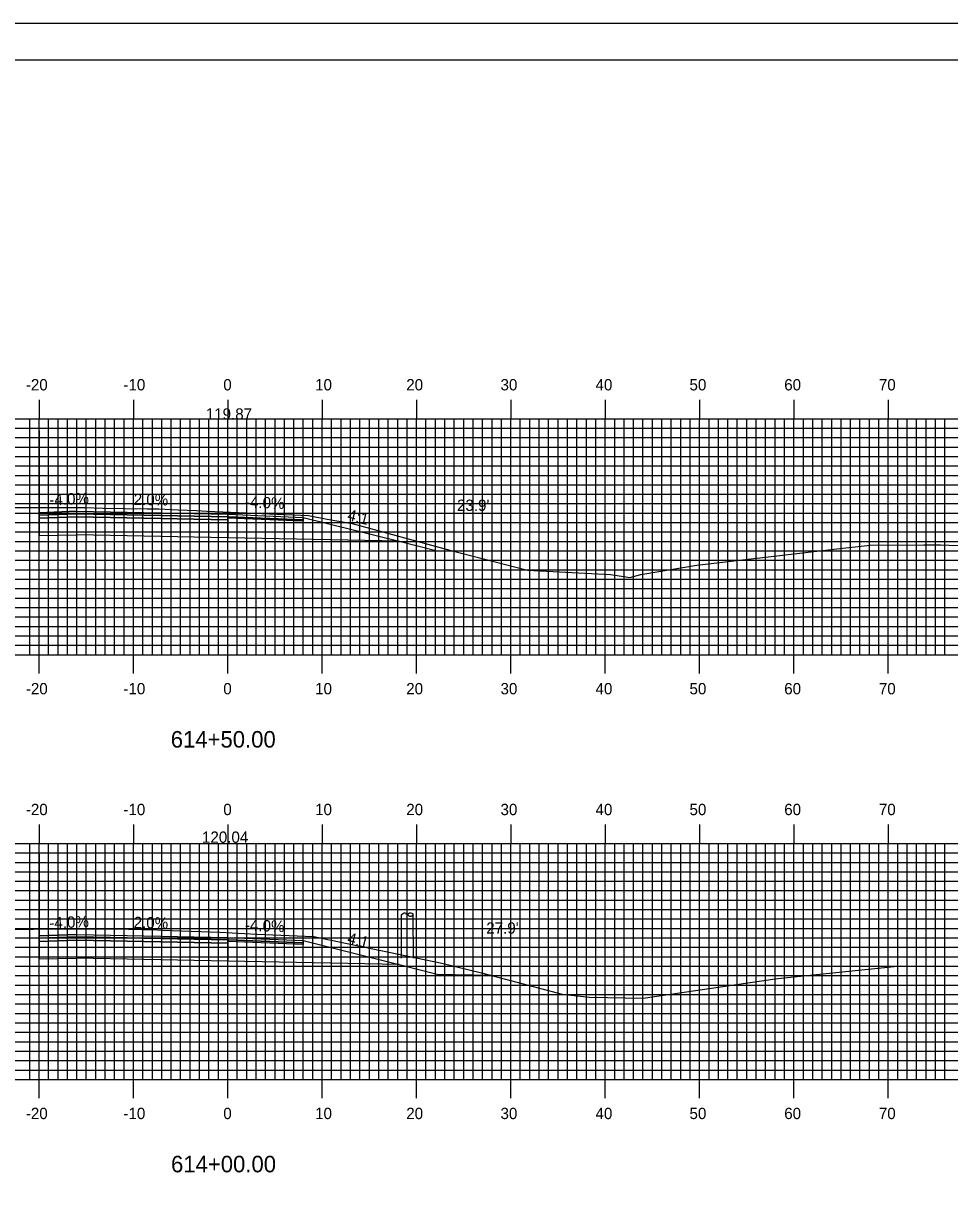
# Model space of a CAD drawing. Extents: x 844143 to 844486, y 363538 to 363758.
# Drawn here: x 844286.8 to 844385, y 363633.7 to 363757.6 of the extents above; entities that cross this region are included whole.
import ezdxf

# ---------------------------------------------------------------- set-up
doc = ezdxf.new("R2010")
doc.units = 0
for name, color, linetype in [('ANNOTATION', 7, 'Continuous'), ('BORDER', 7, 'Continuous'), ('D_Roadway_Centerline', 7, 'Continuous'), ('D_Roadway_Centerline_Text', 7, 'Continuous'), ('D_Roadway_Edge_Shoulder', 7, 'Continuous'), ('D_Roadway_Edge_TW', 7, 'Continuous'), ('D_Roadway_FinishedGrade', 7, 'Continuous'), ('D_Roadway_Pavement', 7, 'Continuous'), ('D_Roadway_SubGrade', 7, 'Continuous'), ('D_Text_Standard', 7, 'Continuous'), ('H_V ANNOTATION', 7, 'Continuous'), ('M_Roadway_Centerline', 7, 'Continuous'), ('MAJOR', 7, 'Continuous'), ('MINOR', 7, 'Continuous'), ('PLOT BOUNDARY', 7, 'Continuous'), ('S_Roadway_Centerline', 7, 'Continuous'), ('S_Utilities_Pole_StreetLight', 7, 'Continuous')]:
    doc.layers.add(name, color=color, linetype=linetype)

msp = doc.modelspace()

# ---------------------------------------------------------------- linework, layer by layer
at = {"layer": 'BORDER'}
msp.add_lwpolyline([(844158.85, 363543.72), (844478.85, 363543.72), (844478.85, 363753.72), (844158.85, 363753.72)], close=True, dxfattribs=at)
at = {"layer": 'D_Roadway_Centerline'}
for points in [[(844288.45, 363705.75), (844288.45, 363705.75), (844292.45, 363705.91), (844308.45, 363705.59), (844316.45, 363705.27), (844326.62, 363702.73)], [(844288.45, 363660.92), (844292.45, 363661.08), (844308.45, 363660.76), (844316.45, 363660.44), (844326.62, 363657.89)]]:
    msp.add_lwpolyline(points, dxfattribs=at)
at = {"layer": 'D_Roadway_Edge_Shoulder'}
for points in [[(844292.45, 363705.91), (844288.45, 363705.75), (844288.45, 363705.5), (844292.45, 363705.66)], [(844308.45, 363705.59), (844316.45, 363705.27), (844316.45, 363705.02), (844308.45, 363705.34)], [(844292.45, 363661.08), (844288.45, 363660.92), (844288.45, 363660.67), (844292.45, 363660.83)], [(844308.45, 363660.76), (844316.45, 363660.44), (844316.45, 363660.19), (844308.45, 363660.51)]]:
    msp.add_lwpolyline(points, close=True, dxfattribs=at)
at = {"layer": 'D_Roadway_Edge_TW'}
for points in [[(844292.45, 363705.91), (844308.45, 363705.59), (844308.45, 363705.34), (844292.45, 363705.66)], [(844292.45, 363661.08), (844308.45, 363660.76), (844308.45, 363660.51), (844292.45, 363660.83)]]:
    msp.add_lwpolyline(points, close=True, dxfattribs=at)
at = {"layer": 'D_Roadway_FinishedGrade'}
for points in [[(844326.62, 363702.73), (844330.62, 363701.73), (844332.31, 363701.7)], [(844326.62, 363657.89), (844330.62, 363656.89), (844336.33, 363656.78)]]:
    msp.add_lwpolyline(points, dxfattribs=at)
at = {"layer": 'D_Roadway_Pavement'}
for points in [[(844292.45, 363705.66), (844288.45, 363705.5), (844288.45, 363705.17), (844292.45, 363705.33)], [(844292.45, 363705.66), (844308.45, 363705.34), (844308.45, 363705.01), (844292.45, 363705.33)], [(844308.45, 363705.34), (844316.45, 363705.02), (844316.45, 363704.86), (844308.45, 363705.18)], [(844292.45, 363660.83), (844288.45, 363660.67), (844288.45, 363660.33), (844292.45, 363660.49)], [(844292.45, 363660.83), (844308.45, 363660.51), (844308.45, 363660.17), (844292.45, 363660.49)], [(844308.45, 363660.51), (844316.45, 363660.19), (844316.45, 363660.02), (844308.45, 363660.34)]]:
    msp.add_lwpolyline(points, close=True, dxfattribs=at)
for points in [[(844308.45, 363705.34), (844308.45, 363705.01)], [(844308.45, 363705.34), (844308.45, 363705.01)], [(844308.45, 363660.51), (844308.45, 363660.17)], [(844308.45, 363660.51), (844308.45, 363660.17)]]:
    msp.add_lwpolyline(points, dxfattribs=at)
at = {"layer": 'D_Roadway_SubGrade'}
for p, q in [((844288.45, 363714.43), (844288.45, 363703.33)), ((844288.45, 363669.59), (844288.45, 363658.5))]:
    msp.add_line(p, q, dxfattribs=at)
for points in [[(844292.45, 363705.33), (844288.45, 363705.17), (844288.45, 363705.5), (844288.45, 363705.75), (844288.45, 363703.33), (844292.45, 363703.41)], [(844292.45, 363705.33), (844308.45, 363705.01), (844308.45, 363703.09), (844292.45, 363703.41)], [(844308.45, 363705.01), (844308.45, 363705.34), (844316.45, 363705.02), (844316.45, 363705.27), (844326.62, 363702.73), (844308.45, 363703.09)], [(844292.45, 363660.49), (844288.45, 363660.33), (844288.45, 363660.67), (844288.45, 363660.92), (844288.45, 363658.5), (844292.45, 363658.58)], [(844292.45, 363660.49), (844308.45, 363660.17), (844308.45, 363658.26), (844292.45, 363658.58)], [(844308.45, 363660.17), (844308.45, 363660.51), (844316.45, 363660.19), (844316.45, 363660.44), (844326.62, 363657.89), (844308.45, 363658.26)]]:
    msp.add_lwpolyline(points, close=True, dxfattribs=at)
at = {"layer": 'MAJOR'}
for p, q in [((844288.45, 363717.73), (844288.45, 363715.72)), ((844298.45, 363717.73), (844298.45, 363715.72)), ((844308.45, 363717.73), (844308.45, 363715.72)), ((844318.45, 363717.73), (844318.45, 363715.72)), ((844328.45, 363717.73), (844328.45, 363715.72)), ((844338.45, 363717.73), (844338.45, 363715.72)), ((844348.45, 363717.73), (844348.45, 363715.72)), ((844358.45, 363717.73), (844358.45, 363715.72)), ((844368.45, 363717.73), (844368.45, 363715.72)), ((844378.45, 363717.73), (844378.45, 363715.72)), ((844168.45, 363715.72), (844448.45, 363715.72)), ((844168.45, 363715.72), (844448.45, 363715.72)), ((844288.45, 363690.72), (844288.45, 363715.72)), ((844298.45, 363690.72), (844298.45, 363715.72)), ((844308.45, 363690.72), (844308.45, 363715.72)), ((844318.45, 363690.72), (844318.45, 363715.72)), ((844328.45, 363690.72), (844328.45, 363715.72)), ((844338.45, 363690.72), (844338.45, 363715.72)), ((844348.45, 363690.72), (844348.45, 363715.72)), ((844358.45, 363690.72), (844358.45, 363715.72)), ((844368.45, 363690.72), (844368.45, 363715.72)), ((844378.45, 363690.72), (844378.45, 363715.72)), ((844168.45, 363710.72), (844448.45, 363710.72)), ((844168.45, 363705.72), (844448.45, 363705.72)), ((844168.45, 363700.72), (844448.45, 363700.72)), ((844168.45, 363695.72), (844448.45, 363695.72)), ((844168.45, 363690.72), (844448.45, 363690.72)), ((844168.45, 363690.72), (844448.45, 363690.72)), ((844288.45, 363688.72), (844288.45, 363690.72)), ((844298.45, 363688.72), (844298.45, 363690.72)), ((844308.45, 363688.72), (844308.45, 363690.72)), ((844318.45, 363688.72), (844318.45, 363690.72)), ((844328.45, 363688.72), (844328.45, 363690.72)), ((844338.45, 363688.72), (844338.45, 363690.72)), ((844348.45, 363688.72), (844348.45, 363690.72)), ((844358.45, 363688.72), (844358.45, 363690.72)), ((844368.45, 363688.72), (844368.45, 363690.72)), ((844378.45, 363688.72), (844378.45, 363690.72)), ((844288.45, 363672.73), (844288.45, 363670.72)), ((844298.45, 363672.73), (844298.45, 363670.72)), ((844308.45, 363672.73), (844308.45, 363670.72)), ((844318.45, 363672.73), (844318.45, 363670.72)), ((844328.45, 363672.73), (844328.45, 363670.72)), ((844338.45, 363672.73), (844338.45, 363670.72)), ((844348.45, 363672.73), (844348.45, 363670.72)), ((844358.45, 363672.73), (844358.45, 363670.72)), ((844368.45, 363672.73), (844368.45, 363670.72)), ((844378.45, 363672.73), (844378.45, 363670.72)), ((844168.45, 363670.72), (844448.45, 363670.72)), ((844168.45, 363670.72), (844448.45, 363670.72)), ((844288.45, 363645.72), (844288.45, 363670.72)), ((844298.45, 363645.72), (844298.45, 363670.72)), ((844308.45, 363645.72), (844308.45, 363670.72)), ((844318.45, 363645.72), (844318.45, 363670.72)), ((844328.45, 363645.72), (844328.45, 363670.72)), ((844338.45, 363645.72), (844338.45, 363670.72)), ((844348.45, 363645.72), (844348.45, 363670.72)), ((844358.45, 363645.72), (844358.45, 363670.72)), ((844368.45, 363645.72), (844368.45, 363670.72)), ((844378.45, 363645.72), (844378.45, 363670.72)), ((844168.45, 363665.72), (844448.45, 363665.72)), ((844168.45, 363660.72), (844448.45, 363660.72)), ((844168.45, 363655.72), (844448.45, 363655.72)), ((844168.45, 363650.72), (844448.45, 363650.72)), ((844168.45, 363645.72), (844448.45, 363645.72)), ((844168.45, 363645.72), (844448.45, 363645.72)), ((844288.45, 363643.72), (844288.45, 363645.72)), ((844298.45, 363643.72), (844298.45, 363645.72)), ((844308.45, 363643.72), (844308.45, 363645.72)), ((844318.45, 363643.72), (844318.45, 363645.72)), ((844328.45, 363643.72), (844328.45, 363645.72)), ((844338.45, 363643.72), (844338.45, 363645.72)), ((844348.45, 363643.72), (844348.45, 363645.72)), ((844358.45, 363643.72), (844358.45, 363645.72)), ((844368.45, 363643.72), (844368.45, 363645.72)), ((844378.45, 363643.72), (844378.45, 363645.72))]:
    msp.add_line(p, q, dxfattribs=at)
at = {"layer": 'MINOR'}
for p, q in [((844287.45, 363690.72), (844287.45, 363715.72)), ((844289.45, 363690.72), (844289.45, 363715.72)), ((844290.45, 363690.72), (844290.45, 363715.72)), ((844291.45, 363690.72), (844291.45, 363715.72)), ((844292.45, 363690.72), (844292.45, 363715.72)), ((844293.45, 363690.72), (844293.45, 363715.72)), ((844294.45, 363690.72), (844294.45, 363715.72)), ((844295.45, 363690.72), (844295.45, 363715.72)), ((844296.45, 363690.72), (844296.45, 363715.72)), ((844297.45, 363690.72), (844297.45, 363715.72)), ((844299.45, 363690.72), (844299.45, 363715.72)), ((844300.45, 363690.72), (844300.45, 363715.72)), ((844301.45, 363690.72), (844301.45, 363715.72)), ((844302.45, 363690.72), (844302.45, 363715.72)), ((844303.45, 363690.72), (844303.45, 363715.72)), ((844304.45, 363690.72), (844304.45, 363715.72)), ((844305.45, 363690.72), (844305.45, 363715.72)), ((844306.45, 363690.72), (844306.45, 363715.72)), ((844307.45, 363690.72), (844307.45, 363715.72)), ((844309.45, 363690.72), (844309.45, 363715.72)), ((844310.45, 363690.72), (844310.45, 363715.72)), ((844311.45, 363690.72), (844311.45, 363715.72)), ((844312.45, 363690.72), (844312.45, 363715.72)), ((844313.45, 363690.72), (844313.45, 363715.72)), ((844314.45, 363690.72), (844314.45, 363715.72)), ((844315.45, 363690.72), (844315.45, 363715.72)), ((844316.45, 363690.72), (844316.45, 363715.72)), ((844317.45, 363690.72), (844317.45, 363715.72)), ((844319.45, 363690.72), (844319.45, 363715.72)), ((844320.45, 363690.72), (844320.45, 363715.72)), ((844321.45, 363690.72), (844321.45, 363715.72)), ((844322.45, 363690.72), (844322.45, 363715.72)), ((844323.45, 363690.72), (844323.45, 363715.72)), ((844324.45, 363690.72), (844324.45, 363715.72)), ((844325.45, 363690.72), (844325.45, 363715.72)), ((844326.45, 363690.72), (844326.45, 363715.72)), ((844327.45, 363690.72), (844327.45, 363715.72)), ((844329.45, 363690.72), (844329.45, 363715.72)), ((844330.45, 363690.72), (844330.45, 363715.72)), ((844331.45, 363690.72), (844331.45, 363715.72)), ((844332.45, 363690.72), (844332.45, 363715.72)), ((844333.45, 363690.72), (844333.45, 363715.72)), ((844334.45, 363690.72), (844334.45, 363715.72)), ((844335.45, 363690.72), (844335.45, 363715.72)), ((844336.45, 363690.72), (844336.45, 363715.72)), ((844337.45, 363690.72), (844337.45, 363715.72)), ((844339.45, 363690.72), (844339.45, 363715.72)), ((844340.45, 363690.72), (844340.45, 363715.72)), ((844341.45, 363690.72), (844341.45, 363715.72)), ((844342.45, 363690.72), (844342.45, 363715.72)), ((844343.45, 363690.72), (844343.45, 363715.72)), ((844344.45, 363690.72), (844344.45, 363715.72)), ((844345.45, 363690.72), (844345.45, 363715.72)), ((844346.45, 363690.72), (844346.45, 363715.72)), ((844347.45, 363690.72), (844347.45, 363715.72)), ((844349.45, 363690.72), (844349.45, 363715.72)), ((844350.45, 363690.72), (844350.45, 363715.72)), ((844351.45, 363690.72), (844351.45, 363715.72)), ((844352.45, 363690.72), (844352.45, 363715.72)), ((844353.45, 363690.72), (844353.45, 363715.72)), ((844354.45, 363690.72), (844354.45, 363715.72)), ((844355.45, 363690.72), (844355.45, 363715.72)), ((844356.45, 363690.72), (844356.45, 363715.72)), ((844357.45, 363690.72), (844357.45, 363715.72)), ((844359.45, 363690.72), (844359.45, 363715.72)), ((844360.45, 363690.72), (844360.45, 363715.72)), ((844361.45, 363690.72), (844361.45, 363715.72)), ((844362.45, 363690.72), (844362.45, 363715.72)), ((844363.45, 363690.72), (844363.45, 363715.72)), ((844364.45, 363690.72), (844364.45, 363715.72)), ((844365.45, 363690.72), (844365.45, 363715.72)), ((844366.45, 363690.72), (844366.45, 363715.72)), ((844367.45, 363690.72), (844367.45, 363715.72)), ((844369.45, 363690.72), (844369.45, 363715.72)), ((844370.45, 363690.72), (844370.45, 363715.72)), ((844371.45, 363690.72), (844371.45, 363715.72)), ((844372.45, 363690.72), (844372.45, 363715.72)), ((844373.45, 363690.72), (844373.45, 363715.72)), ((844374.45, 363690.72), (844374.45, 363715.72)), ((844375.45, 363690.72), (844375.45, 363715.72)), ((844376.45, 363690.72), (844376.45, 363715.72)), ((844377.45, 363690.72), (844377.45, 363715.72)), ((844379.45, 363690.72), (844379.45, 363715.72)), ((844380.45, 363690.72), (844380.45, 363715.72)), ((844381.45, 363690.72), (844381.45, 363715.72)), ((844382.45, 363690.72), (844382.45, 363715.72)), ((844383.45, 363690.72), (844383.45, 363715.72)), ((844384.45, 363690.72), (844384.45, 363715.72)), ((844168.45, 363714.72), (844448.45, 363714.72)), ((844168.45, 363713.72), (844448.45, 363713.72)), ((844168.45, 363712.72), (844448.45, 363712.72)), ((844168.45, 363711.72), (844448.45, 363711.72)), ((844168.45, 363709.72), (844448.45, 363709.72)), ((844168.45, 363708.72), (844448.45, 363708.72)), ((844168.45, 363707.72), (844448.45, 363707.72)), ((844168.45, 363706.72), (844448.45, 363706.72)), ((844168.45, 363704.72), (844448.45, 363704.72)), ((844168.45, 363703.72), (844448.45, 363703.72)), ((844168.45, 363702.72), (844448.45, 363702.72)), ((844168.45, 363701.72), (844448.45, 363701.72)), ((844168.45, 363699.72), (844448.45, 363699.72)), ((844168.45, 363698.72), (844448.45, 363698.72)), ((844168.45, 363697.72), (844448.45, 363697.72)), ((844168.45, 363696.72), (844448.45, 363696.72)), ((844168.45, 363694.72), (844448.45, 363694.72)), ((844168.45, 363693.72), (844448.45, 363693.72)), ((844168.45, 363692.72), (844448.45, 363692.72)), ((844168.45, 363691.72), (844448.45, 363691.72)), ((844168.45, 363669.72), (844448.45, 363669.72)), ((844287.45, 363645.72), (844287.45, 363670.72)), ((844289.45, 363645.72), (844289.45, 363670.72)), ((844290.45, 363645.72), (844290.45, 363670.72)), ((844291.45, 363645.72), (844291.45, 363670.72)), ((844292.45, 363645.72), (844292.45, 363670.72)), ((844293.45, 363645.72), (844293.45, 363670.72)), ((844294.45, 363645.72), (844294.45, 363670.72)), ((844295.45, 363645.72), (844295.45, 363670.72)), ((844296.45, 363645.72), (844296.45, 363670.72)), ((844297.45, 363645.72), (844297.45, 363670.72)), ((844299.45, 363645.72), (844299.45, 363670.72)), ((844300.45, 363645.72), (844300.45, 363670.72)), ((844301.45, 363645.72), (844301.45, 363670.72)), ((844302.45, 363645.72), (844302.45, 363670.72)), ((844303.45, 363645.72), (844303.45, 363670.72)), ((844304.45, 363645.72), (844304.45, 363670.72)), ((844305.45, 363645.72), (844305.45, 363670.72)), ((844306.45, 363645.72), (844306.45, 363670.72)), ((844307.45, 363645.72), (844307.45, 363670.72)), ((844309.45, 363645.72), (844309.45, 363670.72)), ((844310.45, 363645.72), (844310.45, 363670.72)), ((844311.45, 363645.72), (844311.45, 363670.72)), ((844312.45, 363645.72), (844312.45, 363670.72)), ((844313.45, 363645.72), (844313.45, 363670.72)), ((844314.45, 363645.72), (844314.45, 363670.72)), ((844315.45, 363645.72), (844315.45, 363670.72)), ((844316.45, 363645.72), (844316.45, 363670.72)), ((844317.45, 363645.72), (844317.45, 363670.72)), ((844319.45, 363645.72), (844319.45, 363670.72)), ((844320.45, 363645.72), (844320.45, 363670.72)), ((844321.45, 363645.72), (844321.45, 363670.72)), ((844322.45, 363645.72), (844322.45, 363670.72)), ((844323.45, 363645.72), (844323.45, 363670.72)), ((844324.45, 363645.72), (844324.45, 363670.72)), ((844325.45, 363645.72), (844325.45, 363670.72)), ((844326.45, 363645.72), (844326.45, 363670.72)), ((844327.45, 363645.72), (844327.45, 363670.72)), ((844329.45, 363645.72), (844329.45, 363670.72)), ((844330.45, 363645.72), (844330.45, 363670.72)), ((844331.45, 363645.72), (844331.45, 363670.72)), ((844332.45, 363645.72), (844332.45, 363670.72)), ((844333.45, 363645.72), (844333.45, 363670.72)), ((844334.45, 363645.72), (844334.45, 363670.72)), ((844335.45, 363645.72), (844335.45, 363670.72)), ((844336.45, 363645.72), (844336.45, 363670.72)), ((844337.45, 363645.72), (844337.45, 363670.72)), ((844339.45, 363645.72), (844339.45, 363670.72)), ((844340.45, 363645.72), (844340.45, 363670.72)), ((844341.45, 363645.72), (844341.45, 363670.72)), ((844342.45, 363645.72), (844342.45, 363670.72)), ((844343.45, 363645.72), (844343.45, 363670.72)), ((844344.45, 363645.72), (844344.45, 363670.72)), ((844345.45, 363645.72), (844345.45, 363670.72)), ((844346.45, 363645.72), (844346.45, 363670.72)), ((844347.45, 363645.72), (844347.45, 363670.72)), ((844349.45, 363645.72), (844349.45, 363670.72)), ((844350.45, 363645.72), (844350.45, 363670.72)), ((844351.45, 363645.72), (844351.45, 363670.72)), ((844352.45, 363645.72), (844352.45, 363670.72)), ((844353.45, 363645.72), (844353.45, 363670.72)), ((844354.45, 363645.72), (844354.45, 363670.72)), ((844355.45, 363645.72), (844355.45, 363670.72)), ((844356.45, 363645.72), (844356.45, 363670.72)), ((844357.45, 363645.72), (844357.45, 363670.72)), ((844359.45, 363645.72), (844359.45, 363670.72)), ((844360.45, 363645.72), (844360.45, 363670.72)), ((844361.45, 363645.72), (844361.45, 363670.72)), ((844362.45, 363645.72), (844362.45, 363670.72)), ((844363.45, 363645.72), (844363.45, 363670.72)), ((844364.45, 363645.72), (844364.45, 363670.72)), ((844365.45, 363645.72), (844365.45, 363670.72)), ((844366.45, 363645.72), (844366.45, 363670.72)), ((844367.45, 363645.72), (844367.45, 363670.72)), ((844369.45, 363645.72), (844369.45, 363670.72)), ((844370.45, 363645.72), (844370.45, 363670.72)), ((844371.45, 363645.72), (844371.45, 363670.72)), ((844372.45, 363645.72), (844372.45, 363670.72)), ((844373.45, 363645.72), (844373.45, 363670.72)), ((844374.45, 363645.72), (844374.45, 363670.72)), ((844375.45, 363645.72), (844375.45, 363670.72)), ((844376.45, 363645.72), (844376.45, 363670.72)), ((844377.45, 363645.72), (844377.45, 363670.72)), ((844379.45, 363645.72), (844379.45, 363670.72)), ((844380.45, 363645.72), (844380.45, 363670.72)), ((844381.45, 363645.72), (844381.45, 363670.72)), ((844382.45, 363645.72), (844382.45, 363670.72)), ((844383.45, 363645.72), (844383.45, 363670.72)), ((844384.45, 363645.72), (844384.45, 363670.72)), ((844168.45, 363668.72), (844448.45, 363668.72)), ((844168.45, 363667.72), (844448.45, 363667.72)), ((844168.45, 363666.72), (844448.45, 363666.72)), ((844168.45, 363664.72), (844448.45, 363664.72)), ((844168.45, 363663.72), (844448.45, 363663.72)), ((844168.45, 363662.72), (844448.45, 363662.72)), ((844168.45, 363661.72), (844448.45, 363661.72)), ((844168.45, 363659.72), (844448.45, 363659.72)), ((844168.45, 363658.72), (844448.45, 363658.72)), ((844168.45, 363657.72), (844448.45, 363657.72)), ((844168.45, 363656.72), (844448.45, 363656.72)), ((844168.45, 363654.72), (844448.45, 363654.72)), ((844168.45, 363653.72), (844448.45, 363653.72)), ((844168.45, 363652.72), (844448.45, 363652.72)), ((844168.45, 363651.72), (844448.45, 363651.72)), ((844168.45, 363649.72), (844448.45, 363649.72)), ((844168.45, 363648.72), (844448.45, 363648.72)), ((844168.45, 363647.72), (844448.45, 363647.72)), ((844168.45, 363646.72), (844448.45, 363646.72))]:
    msp.add_line(p, q, dxfattribs=at)
at = {"layer": 'PLOT BOUNDARY'}
msp.add_lwpolyline([(844142.66, 363537.6), (844482.66, 363537.6), (844482.66, 363757.6), (844142.66, 363757.6)], close=True, dxfattribs=at)
at = {"layer": 'S_Roadway_Centerline'}
for points in [[(844282.64, 363706.33), (844293.29, 363706.3), (844295.24, 363706.26), (844299.9, 363706.18), (844301.13, 363706.16), (844303.2, 363706.05), (844305.14, 363705.98), (844306.27, 363705.93), (844317, 363705.47), (844318.97, 363705.09), (844321.64, 363704.62), (844331.99, 363701.78), (844340.21, 363699.69), (844349.02, 363699.2), (844350.63, 363698.96), (844351.07, 363698.89), (844352.24, 363699.21), (844358.17, 363700.19), (844372.98, 363701.95), (844376.52, 363702.32), (844382.2, 363702.37), (844384, 363702.36), (844384.9, 363702.32), (844395.61, 363702.04)], [(844283.29, 363661.6), (844292.36, 363661.69), (844296.4, 363661.67), (844300.99, 363661.57), (844301.51, 363661.55), (844307.6, 363661.31), (844311.52, 363661.12), (844317.5, 363660.86), (844317.51, 363660.86), (844317.55, 363660.85), (844318.37, 363660.68), (844331.14, 363658.05), (844335.32, 363657.03), (844343.88, 363654.74), (844346.77, 363654.45), (844352.48, 363654.34), (844366.46, 363656.37), (844366.54, 363656.39), (844366.73, 363656.42), (844379.75, 363657.74), (844386.66, 363657.73)]]:
    msp.add_lwpolyline(points, dxfattribs=at)
at = {"layer": 'S_Utilities_Pole_StreetLight'}
for p, q in [((844326.87, 363658.56), (844326.86, 363663.18)), ((844326.87, 363663.18), (844327.02, 363663.29)), ((844327.33, 363663.29), (844327.49, 363663.18)), ((844327.65, 363663.29), (844327.49, 363663.18)), ((844327.49, 363663.18), (844327.65, 363663.06)), ((844328.12, 363663.18), (844327.96, 363663.29)), ((844327.96, 363663.06), (844328.12, 363663.18)), ((844328.12, 363658.56), (844328.11, 363663.18))]:
    msp.add_line(p, q, dxfattribs=at)
for centre, start, end in [((844327.18, 363663.07), 90, 125.2644), ((844327.18, 363663.07), 54.7356, 90), ((844327.8, 363663.07), 90, 125.2644), ((844327.8, 363663.07), 54.7356, 90), ((844327.8, 363663.29), 234.7356, 270), ((844327.8, 363663.29), 270, 305.2644)]:
    msp.add_arc(centre, 0.271, start, end, dxfattribs=at)

# ---------------------------------------------------------------- texts
at = {"layer": 'ANNOTATION'}
for s, rotation, p in [('-4.0%', 2.2906, (844289.56, 363706.54)), ('2.0%', 358.8542, (844298.46, 363706.59)), ('-4.0%', 357.7094, (844310.24, 363706.32)), ('4:1', 345.9638, (844321.04, 363704.99)), ('-4.0%', 2.2906, (844289.55, 363661.7)), ('2.0%', 358.8542, (844298.46, 363661.76)), ('-4.0%', 357.7094, (844310.24, 363661.49)), ('4:1', 345.9638, (844321.04, 363660.15))]:
    msp.add_text(s, height=1.2, rotation=rotation, dxfattribs=at).set_placement(p)
at = {"layer": 'D_Roadway_Centerline_Text'}
for s, p in [('119.87', (844306.11, 363715.62)), ('120.04', (844305.71, 363670.79))]:
    msp.add_text(s, height=1.2, dxfattribs=at).set_placement(p)
at = {"layer": 'D_Text_Standard'}
for s, p in [("23.9'", (844332.74, 363705.95)), ("27.9'", (844335.84, 363661.16))]:
    msp.add_text(s, height=1.2, dxfattribs=at).set_placement(p)
at = {"layer": 'H_V ANNOTATION'}
for s, height, p in [('-20', 1.2, (844287.04, 363718.72)), ('-10', 1.2, (844297.38, 363718.72)), ('0', 1.2, (844307.97, 363718.72)), ('10', 1.2, (844317.7, 363718.72)), ('20', 1.2, (844327.36, 363718.72)), ('30', 1.2, (844337.35, 363718.72)), ('40', 1.2, (844347.42, 363718.72)), ('50', 1.2, (844357.38, 363718.72)), ('60', 1.2, (844367.42, 363718.72)), ('70', 1.2, (844377.45, 363718.72)), ('-20', 1.2, (844287.04, 363686.52)), ('-10', 1.2, (844297.38, 363686.52)), ('0', 1.2, (844307.97, 363686.52)), ('10', 1.2, (844317.7, 363686.52)), ('20', 1.2, (844327.36, 363686.52)), ('30', 1.2, (844337.35, 363686.52)), ('40', 1.2, (844347.42, 363686.52)), ('50', 1.2, (844357.38, 363686.52)), ('60', 1.2, (844367.42, 363686.52)), ('70', 1.2, (844377.45, 363686.52)), ('614+50.00', 1.75, (844302.4, 363680.88)), ('-20', 1.2, (844287.04, 363673.72)), ('-10', 1.2, (844297.38, 363673.72)), ('0', 1.2, (844307.97, 363673.72)), ('10', 1.2, (844317.7, 363673.72)), ('20', 1.2, (844327.36, 363673.72)), ('30', 1.2, (844337.35, 363673.72)), ('40', 1.2, (844347.42, 363673.72)), ('50', 1.2, (844357.38, 363673.72)), ('60', 1.2, (844367.42, 363673.72)), ('70', 1.2, (844377.45, 363673.72)), ('-20', 1.2, (844287.04, 363641.52)), ('-10', 1.2, (844297.38, 363641.52)), ('0', 1.2, (844307.97, 363641.52)), ('10', 1.2, (844317.7, 363641.52)), ('20', 1.2, (844327.36, 363641.52)), ('30', 1.2, (844337.35, 363641.52)), ('40', 1.2, (844347.42, 363641.52)), ('50', 1.2, (844357.38, 363641.52)), ('60', 1.2, (844367.42, 363641.52)), ('70', 1.2, (844377.45, 363641.52)), ('614+00.00', 1.75, (844302.43, 363635.88))]:
    msp.add_text(s, height=height, dxfattribs=at).set_placement(p)
at = {"layer": 'M_Roadway_Centerline'}
for s, p in [('C', (844301.12, 363706.16)), ('L', (844301.13, 363706.15)), ('C', (844300.98, 363661.57)), ('L', (844300.99, 363661.57))]:
    msp.add_text(s, height=0.0146, dxfattribs=at).set_placement(p)

doc.saveas('drawing.dxf')
